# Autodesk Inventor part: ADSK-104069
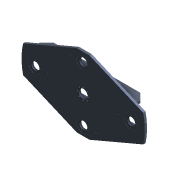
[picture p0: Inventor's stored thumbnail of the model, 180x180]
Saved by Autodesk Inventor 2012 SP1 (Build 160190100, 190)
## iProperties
Shininess: 0.0
Created: 2000-10
Part Number: ADSK-104069
Document SubType Name: Modeling
Stock Number: ADSK-104069
Density: 1 g/cm^3
Material: Default
Density: 0.0
Volumn: 0.0
Area: 0.0
PropertySet Name: Model Information
Control State: 0
Master: False
Checked Out: False
Author: gao
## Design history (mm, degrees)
node "Extrusion1" dims "d1" = 25.4, "d2" = 0
  sketch "Sketch1"
    geometry: C1 r 685.8 at (0, 0)
    constraints: 1 centre point
    dimensions: "d0" = 1371.6 diameter of C1
node "Hole1" dims "d3" = 101.6, "d4" = 9.525, "d5" = 6.35, "d6" = 60 deg, "d7" = 19.05, "d8" = 118 deg
  sketch "Sketch2"
    geometry: C1 r 685.8 at (0, 0) reference; 1 further point
    constraints: 1 coincident
node "Hole2" dims "d11" = 90, "d12" = 9.525, "d13" = 6.35, "d14" = 60 deg, "d15" = 19.05, "d16" = 118 deg
  sketch "Sketch3"
    geometry: C1 r 50.8 at (0, 0) reference; 2 further points
    dimensions: "d9" = 533.4 distance of C1.centre point (-533.4, 0); "d10" = 533.4 distance of point (533.4, 0) C1.centre (= d9)
node "Extrusion2" dims "d21" = 127, "d22" = 0
  sketch "Sketch4"
    geometry: L1 (-558.8, 177.8)-(558.8, 177.8); L2 (558.8, 177.8)-(558.8, 152.4); L3 (558.8, 152.4)-(-558.8, 152.4); L4 (-558.8, 152.4)-(-558.8, 177.8); C1 r 50.8 at (0, 0) reference
    constraints: 8 end point, 2 parallel, 1 horizontal, 1 perpendicular
    dimensions: "d17" = 25.4 distance of L1.end L2.end; "d18" = 1117.6 distance of L1.start L1.end; "d19" = 558.8 horizontal distance of L1.start C1.centre; "d20" = 152.4 distance from line of L3 C1.centre
workaxis "Work Axis1"
workplane "Work Plane1"
node "Mirror1"
node "Hole3" dims "d31" = 10.3124, "d32" = 14.224, "d33" = 9.525, "d34" = 60 deg, "d35" = 19.05, "d36" = 118 deg
  sketch "Sketch6" dims "d30" = 123.825
    geometry: A1 r 685.8 centre (0, 0) between (-637.029, 254) and (-637.029, -254) reference; 2 further points
    constraints: 1 coincident, 1 vertical alignment, 2 other
node "Circular Pattern1" dims "d37" = 80, "d39" = 45 deg
node "Extrusion4" dims "d55" = 1.524, "d56" = 0
  sketch "Sketch8"
    geometry: C1 r 5.156 at (-61.913, 0) reference; C2 r 5.156 at (-43.779, -43.779) reference; C3 r 5.156 at (0, -61.913) reference; C4 r 5.156 at (43.779, -43.779) reference; C5 r 5.156 at (61.913, 0) reference; C6 r 5.156 at (43.779, 43.779) reference; C7 r 5.156 at (-43.779, 43.779) reference; C8 r 5.156 at (0, 61.913) reference; C9 r 50.8 at (0, 0) reference; C10 r 79.375 at (0, 0)
    constraints: 1 centre point, 1 coincident
    dimensions: "d54" = 158.75 diameter of C10
workplane "Work Plane2"
node "Extrusion6" dims "d71" = 127, "d72" = 0
  sketch "Sketch11"
    geometry: L1 (558.8, 152.4)-(-558.8, 152.4) reference; L2 (-558.8, -152.4)-(558.8, -152.4) reference; L3 (558.8, -152.4)-(558.8, -177.8) reference; L4 (-330.2, 152.4)-(-330.2, -152.4); L5 (-304.8, 152.4)-(-304.8, -152.4); A1 r 685.8 centre (0, 0) between (-661.275, 181.76) and (-661.275, -181.76) reference
    constraints: 4 end point, 4 point on line, 1 parallel, 1 perpendicular
    dimensions: "d69" = 25.4 distance between parallel lines of L4 L5; "d70" = 304.8 distance from line of L5 A1.centre
node "Mirror7"
node "Extrusion7" dims "d83" = 1.524, "d84" = 0
  sketch "Sketch13"
    geometry: C1 r 3.899 at (-614.222, 80.822) reference; C2 r 3.899 at (-562.983, 110.405) reference; C3 r 3.899 at (-503.817, 110.405) reference; C4 r 3.899 at (-452.578, 80.822) reference; C5 r 3.899 at (-422.995, 29.583) reference; C6 r 3.899 at (-422.995, -29.583) reference; C7 r 3.899 at (-452.578, -80.822) reference; C8 r 3.899 at (-503.817, -110.405) reference; C9 r 3.899 at (-562.983, -110.405) reference; C10 r 3.899 at (-614.222, -80.822) reference; C11 r 3.899 at (-643.805, 29.583) reference; C12 r 3.899 at (-643.805, -29.583) reference; C13 r 3.899 at (614.222, -80.822) reference; C14 r 3.899 at (562.983, -110.405) reference; C15 r 3.899 at (503.817, -110.405) reference; C16 r 3.899 at (452.578, -80.822) reference; C17 r 3.899 at (422.995, -29.583) reference; C18 r 3.899 at (422.995, 29.583) reference; C19 r 3.899 at (452.578, 80.822) reference; C20 r 3.899 at (503.817, 110.405) reference; C21 r 3.899 at (562.983, 110.405) reference; C22 r 3.899 at (614.222, 80.822) reference; C23 r 3.899 at (643.805, -29.583) reference; C24 r 3.899 at (643.805, 29.583) reference; C25 r 45 at (-533.4, 0) reference; C26 r 45 at (533.4, 0) reference; C27 r 76.2 at (533.4, 0); C28 r 76.2 at (-533.4, 0)
    constraints: 2 centre point, 2 coincident
    dimensions: "d81" = 152.4 diameter of C28; "d82" = 152.4 diameter of C27 (= d81)
node "Hole7" dims "d90" = 90, "d91" = 9.525, "d92" = 6.35, "d93" = 60 deg, "d94" = 19.05, "d95" = 118 deg
  sketch "Sketch15"
    geometry: C1 r 50.8 at (0, 0) reference; 2 further points
    dimensions: "d88" = 304.8 distance of point (0, 304.8) C1.centre; "d89" = 304.8 distance of point (0, -304.8) C1.centre (= d88)
node "Extrusion9" dims "d99" = 25.4, "d100" = 0
  sketch "Sketch16"
    geometry: L1 (-552.414, 406.4)-(552.414, 406.4); L2 (-552.414, -406.4)-(552.414, -406.4); C1 r 50.8 at (0, 0) reference; A1 r 685.8 centre (0, 0) between (-552.414, 406.4) and (552.414, 406.4) reference
    constraints: 4 end point, 4 point on circle, 1 horizontal, 1 parallel
    dimensions: "d96" = 406.4 distance from line of L1 C1.centre; "d98" = 406.4 distance from line of C1.centre L2 (= d96)
node "Extrusion10" dims "d103" = 25.4, "d104" = 0
  sketch "Sketch17"
    geometry: L1 (552.414, 406.4)-(-552.414, 406.4) reference; L2 (-668.652, 152.4)-(-70.266, 406.4); A1 r 685.8 centre (0, 0) between (-552.414, 406.4) and (-552.414, -406.4) reference
    constraints: 2 end point, 1 point on circle, 1 point on line
    dimensions: "d101" = 152.4 vertical distance of L2.start A1.centre; "d102" = 23 deg angle of L1 L2
node "Circular Pattern4" dims "d105" = 20, "d107" = 180 deg
node "Mirror8"
node "Chamfer2" dims "d108" = 76.2, "d109" = 76.2, "d161" = 45 deg
node "Extrusion11" dims "d112" = 1.524, "d113" = 0
  sketch "Sketch18"
    geometry: C1 r 45 at (0, 304.8) reference; C2 r 45 at (0, -304.8) reference; C3 r 76.2 at (0, 304.8); C4 r 76.2 at (0, -304.8)
    constraints: 2 centre point, 2 coincident
    dimensions: "d110" = 152.4 diameter of C3; "d111" = 152.4 diameter of C4 (= d110)
node "Hole8" dims "d116" = 7.7978, "d117" = 9.525, "d118" = 6.35, "d119" = 60 deg, "d120" = 31.75, "d121" = 118 deg, "d157" = 19.05
  sketch "Sketch19"
    geometry: C1 r 45 at (0, 304.8) reference; 2 further points
    dimensions: "d114" = 133.35 distance of C1.centre point (133.35, 304.8); "d115" = 25.4 distance of point (133.35, 304.8) point (158.75, 304.8)
node "Circular Pattern5" dims "d122" = 20, "d124" = 180 deg
node "Hole9" dims "d127" = 7.7978, "d128" = 9.525, "d129" = 6.35, "d130" = 60 deg, "d131" = 31.75, "d132" = 118 deg, "d158" = 19.05
  sketch "Sketch20"
    geometry: C1 r 45 at (533.4, 0) reference; 2 further points
    dimensions: "d125" = 133.35 distance of point (400.05, 0) C1.centre; "d126" = 25.4 distance of point (400.05, 0) point (374.65, 0)
node "Circular Pattern6" dims "d133" = 20, "d135" = 180 deg
node "Hole10" dims "d136" = 6.4008, "d137" = 9.525, "d138" = 6.35, "d139" = 60 deg, "d140" = 19.05, "d141" = 118 deg, "d159" = 12.7
  sketch "Sketch21"
    geometry: C1 r 3.899 at (-24.394, 357.114) reference; C2 r 3.899 at (-52.314, 280.406) reference; C3 r 3.899 at (24.394, 252.486) reference; C4 r 3.899 at (52.314, 329.194) reference; C5 r 3.899 at (52.314, -280.406) reference; C6 r 3.899 at (-24.394, -252.486) reference; C7 r 3.899 at (-52.314, -329.194) reference; C8 r 3.899 at (24.394, -357.114) reference; 8 further points
    constraints: 8 coincident
node "Hole11" dims "d145" = 7.7978, "d146" = 9.525, "d147" = 6.35, "d148" = 60 deg, "d149" = 19.05, "d150" = 118 deg, "d160" = 12.7
  sketch "Sketch22"
    geometry: L1 (558.8, 152.4)-(330.2, 152.4) reference; L2 (-533.4, 0)-(-496.44, 44.048); L3 (-533.4, 0)-(-476.119, 5.011); L4 (-533.4, 0)-(-400.05, 0); C1 r 3.899 at (-400.05, 0) reference; C2 r 45 at (-533.4, 0) reference; A1 r 57.5 centre (-533.4, 0) between (-496.44, 44.048) and (-476.119, 5.011); 1 further point
    constraints: 6 end point, 2 point on circle, 1 centre point, 1 coincident, 1 parallel
    dimensions: "d142" = 115 diameter of A1; "d143" = 50 deg angle of L2 L4; "d144" = 45 deg angle of L3 L2
node "Circular Pattern7" dims "d151" = 40, "d153" = 90 deg
node "Rectangular Pattern1" dims "d154" = 20, "d156" = 1066.8
body "Solid1"
other parameters: "d23" = 0, "d62" = 0
